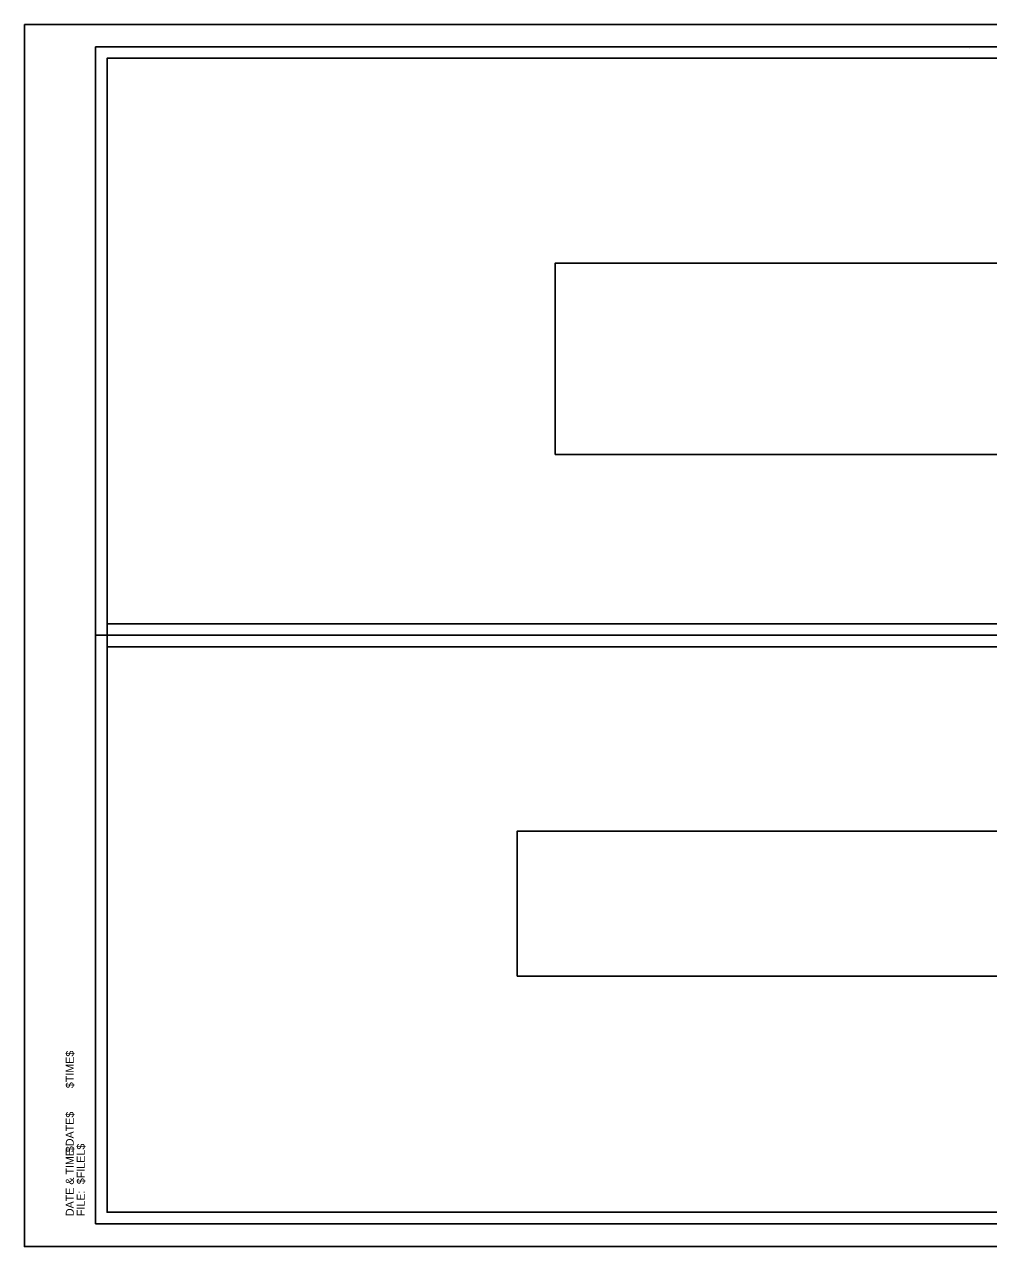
# Model space of a CAD drawing. Extents: x 1369905 to 1370238, y 380119 to 380332.
# Drawn here: x 1369904.7 to 1370072.9, y 380119.1 to 380332.4 of the extents above; entities that cross this region are included whole.
import ezdxf

# ---------------------------------------------------------------- set-up
doc = ezdxf.new("R2010")
doc.units = 0
for name, color, linetype in [('Default', 7, 'Continuous'), ('R_Border', 7, 'Continuous'), ('R_Border Notes', 7, 'Continuous'), ('R_Border Plan-Plan', 7, 'Continuous'), ('R_No Plot', 7, 'Continuous')]:
    doc.layers.add(name, color=color, linetype=linetype)

msp = doc.modelspace()

# ---------------------------------------------------------------- linework, layer by layer
at = {"layer": 'Default'}
for points in [[(1369997.28, 380257.3), (1370141.89, 380257.3), (1370141.89, 380290.72), (1369997.28, 380290.72)], [(1369990.65, 380166.28), (1370148.52, 380166.28), (1370148.52, 380191.55), (1369990.65, 380191.55)]]:
    msp.add_lwpolyline(points, close=True, dxfattribs=at)
at = {"layer": 'R_Border'}
for p, q in [((1369917.07, 380328.5), (1370233.25, 380328.5)), ((1369917.07, 380123.04), (1369917.07, 380328.5)), ((1370069.59, 380328.24), (1370069.59, 380328.24)), ((1370069.59, 380328.24), (1370069.59, 380328.24)), ((1369917.07, 380123.04), (1369917.07, 380123.04)), ((1370233.25, 380123.04), (1369917.07, 380123.04))]:
    msp.add_line(p, q, dxfattribs=at)
at = {"layer": 'R_Border Plan-Plan'}
msp.add_line((1369917.07, 380225.77), (1370233.25, 380225.77), dxfattribs=at)
at = {"layer": 'R_No Plot'}
for points in [[(1369904.66, 380332.4), (1370238, 380332.4), (1370238, 380119.06), (1369904.66, 380119.06)], [(1370231.25, 380227.77), (1369919.07, 380227.77), (1369919.07, 380326.5), (1370168.61, 380326.5), (1370168.61, 380316.62), (1370186.15, 380316.62), (1370210.25, 380316.62), (1370210.25, 380294.29), (1370231.25, 380294.29)], [(1369919.07, 380326.5), (1370168.61, 380326.5), (1370168.61, 380316.62), (1370186.15, 380316.62), (1370210.25, 380316.62), (1370210.25, 380294.29), (1370231.25, 380294.29), (1370231.25, 380125.04), (1369919.07, 380125.04)], [(1369919.07, 380223.77), (1370231.25, 380223.77), (1370231.25, 380125.04), (1369919.07, 380125.04)]]:
    msp.add_lwpolyline(points, close=True, dxfattribs=at)

# ---------------------------------------------------------------- texts
at = {"layer": 'R_Border Notes'}
for s, height, p in [('$TIME$', 1.397, (1369913.27, 380146.71)), ('$DATE$', 1.397, (1369913.27, 380135.54)), ('DATE & TIME:', 1.3968, (1369913.27, 380124.37)), ('$FILEL$', 1.397, (1369915.19, 380129.95)), ('FILE: ', 1.397, (1369915.19, 380124.37))]:
    msp.add_text(s, height=height, rotation=90, dxfattribs=at).set_placement(p)

doc.saveas('drawing.dxf')
